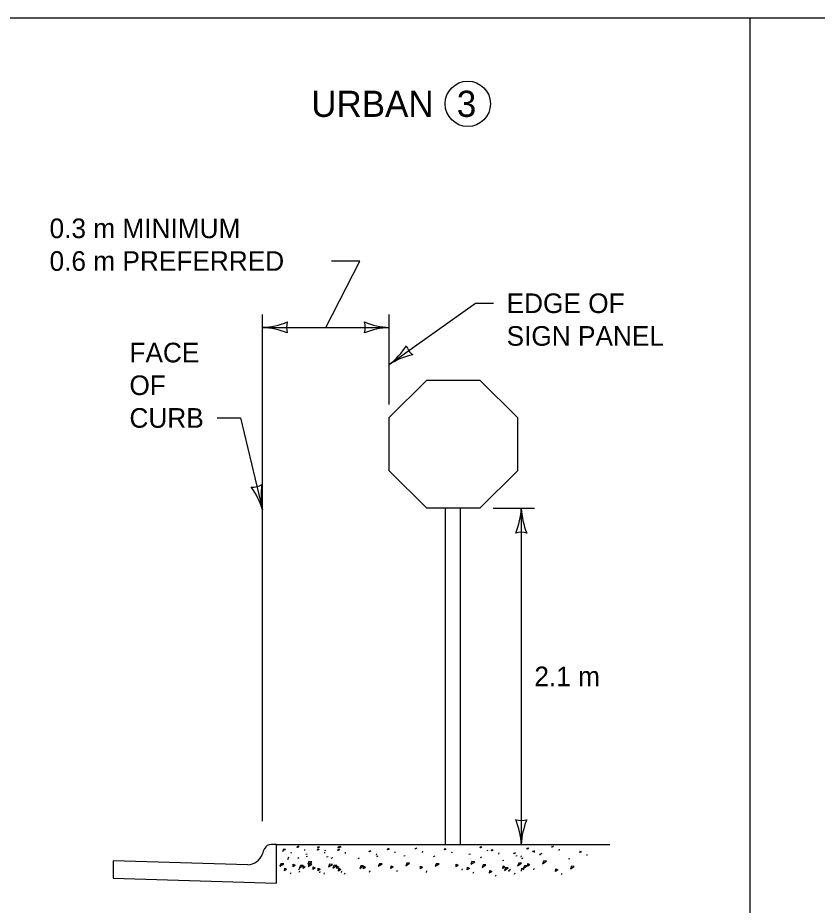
# Model space of a CAD drawing. Extents: x 49991.4 to 50021, y 49987.6 to 50011.4.
# Drawn here: x 50005.827 to 50008.273, y 49996.284 to 49998.999 of the extents above; entities that cross this region are included whole.
import ezdxf

# ---------------------------------------------------------------- set-up
doc = ezdxf.new("R2010")
doc.units = 0
for name, color, linetype in [('Level 1', 7, 'Continuous'), ('Level 2', 7, 'Continuous'), ('Level 3', 7, 'Continuous')]:
    doc.layers.add(name, color=color, linetype=linetype)

msp = doc.modelspace()

# ---------------------------------------------------------------- linework, layer by layer
at = {"layer": 'Level 1'}
for p, q in [((50007.1354, 49996.4699), (50007.1354, 49997.4987)), ((50007.1816, 49996.4699), (50007.1816, 49997.4987)), ((50006.6189, 49996.4699), (50006.6019, 49996.4699)), ((50006.6189, 49996.4699), (50007.6386, 49996.4699)), ((50006.6189, 49996.3514), (50006.6189, 49996.4699)), ((50006.6402, 49996.4554), (50006.637, 49996.4475)), ((50006.6411, 49996.4529), (50006.6431, 49996.4577)), ((50006.6456, 49996.454), (50006.6411, 49996.4529)), ((50006.6431, 49996.4577), (50006.6456, 49996.454)), ((50006.682, 49996.4609), (50006.684, 49996.4657)), ((50006.6865, 49996.462), (50006.682, 49996.4609)), ((50006.684, 49996.4657), (50006.6865, 49996.462)), ((50006.7049, 49996.4514), (50006.7054, 49996.455)), ((50006.7436, 49996.4529), (50006.7456, 49996.4577)), ((50006.7481, 49996.454), (50006.7436, 49996.4529)), ((50006.7449, 49996.46), (50006.7469, 49996.4648)), ((50006.7494, 49996.4611), (50006.7449, 49996.46)), ((50006.7456, 49996.4577), (50006.7481, 49996.454)), ((50006.7469, 49996.4648), (50006.7494, 49996.4611)), ((50006.7678, 49996.4505), (50006.7683, 49996.4541)), ((50006.8065, 49996.452), (50006.8085, 49996.4568)), ((50006.811, 49996.4531), (50006.8065, 49996.452)), ((50006.8074, 49996.46), (50006.8094, 49996.4648)), ((50006.8119, 49996.4611), (50006.8074, 49996.46)), ((50006.8085, 49996.4568), (50006.811, 49996.4531)), ((50006.8111, 49996.4609), (50006.8131, 49996.4657)), ((50006.8156, 49996.462), (50006.8111, 49996.4609)), ((50006.8131, 49996.4657), (50006.8156, 49996.462)), ((50006.9018, 49996.4473), (50006.9039, 49996.452)), ((50006.9039, 49996.452), (50006.9063, 49996.4484)), ((50006.9587, 49996.4537), (50006.9607, 49996.4585)), ((50006.9632, 49996.4548), (50006.9587, 49996.4537)), ((50006.9607, 49996.4585), (50006.9632, 49996.4548)), ((50007.0425, 49996.4553), (50007.0446, 49996.46)), ((50007.0446, 49996.46), (50007.047, 49996.4564)), ((50007.1326, 49996.4537), (50007.1347, 49996.4585)), ((50007.1371, 49996.4548), (50007.1326, 49996.4537)), ((50007.1347, 49996.4585), (50007.1371, 49996.4548)), ((50007.2416, 49996.46), (50007.2437, 49996.4648)), ((50007.2461, 49996.4611), (50007.2416, 49996.46)), ((50007.2437, 49996.4648), (50007.2461, 49996.4611)), ((50007.2646, 49996.4505), (50007.265, 49996.4541)), ((50007.276, 49996.4505), (50007.278, 49996.4552)), ((50007.2805, 49996.4515), (50007.276, 49996.4505)), ((50007.278, 49996.4552), (50007.2805, 49996.4515)), ((50007.385, 49996.4553), (50007.3871, 49996.46)), ((50007.3895, 49996.4564), (50007.385, 49996.4553)), ((50007.3871, 49996.46), (50007.3895, 49996.4564)), ((50007.4024, 49996.4473), (50007.4044, 49996.452)), ((50007.4044, 49996.452), (50007.4068, 49996.4484)), ((50007.4608, 49996.4616), (50007.4629, 49996.4663)), ((50007.4653, 49996.4627), (50007.4608, 49996.4616)), ((50007.4629, 49996.4663), (50007.4653, 49996.4627)), ((50007.4837, 49996.452), (50007.4842, 49996.4557)), ((50007.5462, 49996.4457), (50007.5483, 49996.4505)), ((50007.5483, 49996.4505), (50007.5507, 49996.4468)), ((50006.6551, 49996.4314), (50006.6519, 49996.4235)), ((50006.664, 49996.4433), (50006.6645, 49996.447)), ((50006.6871, 49996.4287), (50006.6824, 49996.4271)), ((50006.7128, 49996.4405), (50006.7082, 49996.4389)), ((50006.7136, 49996.4334), (50006.709, 49996.4318)), ((50006.7665, 49996.4433), (50006.767, 49996.447)), ((50006.7765, 49996.4325), (50006.7719, 49996.4309)), ((50006.7896, 49996.4287), (50006.7849, 49996.4271)), ((50006.8294, 49996.4424), (50006.8299, 49996.4461)), ((50006.8719, 49996.4278), (50006.8672, 49996.4262)), ((50006.9063, 49996.4484), (50006.9018, 49996.4473)), ((50006.9287, 49996.4342), (50006.9241, 49996.4326)), ((50006.9247, 49996.4377), (50006.9252, 49996.4414)), ((50006.9816, 49996.4441), (50006.9821, 49996.4478)), ((50007.0125, 49996.4358), (50007.0079, 49996.4342)), ((50007.0654, 49996.4457), (50007.0659, 49996.4494)), ((50007.1026, 49996.4342), (50007.098, 49996.4326)), ((50007.1555, 49996.4441), (50007.156, 49996.4478)), ((50007.2117, 49996.4405), (50007.2071, 49996.4389)), ((50007.246, 49996.4309), (50007.2414, 49996.4293)), ((50007.2989, 49996.4409), (50007.2994, 49996.4445)), ((50007.3444, 49996.441), (50007.3464, 49996.4457)), ((50007.3488, 49996.4421), (50007.3444, 49996.441)), ((50007.3464, 49996.4457), (50007.3488, 49996.4421)), ((50007.3551, 49996.4358), (50007.3504, 49996.4342)), ((50007.3673, 49996.4314), (50007.3678, 49996.435)), ((50007.3724, 49996.4278), (50007.3678, 49996.4262)), ((50007.4068, 49996.4484), (50007.4024, 49996.4473)), ((50007.4079, 49996.4457), (50007.4084, 49996.4494)), ((50007.4253, 49996.4377), (50007.4258, 49996.4414)), ((50007.4309, 49996.4421), (50007.4262, 49996.4405)), ((50007.5162, 49996.4262), (50007.5116, 49996.4246)), ((50007.5507, 49996.4468), (50007.5462, 49996.4457)), ((50007.5691, 49996.4361), (50007.5696, 49996.4398)), ((50006.5306, 49996.4081), (50006.1189, 49996.4205)), ((50006.1189, 49996.4205), (50006.1189, 49996.3665)), ((50006.6319, 49996.4112), (50006.6287, 49996.4033)), ((50006.6287, 49996.4033), (50006.6408, 49996.4109)), ((50006.6408, 49996.4109), (50006.6319, 49996.4112)), ((50006.6434, 49996.3897), (50006.6439, 49996.398)), ((50006.6439, 49996.398), (50006.6497, 49996.3947)), ((50006.6692, 49996.4016), (50006.6696, 49996.4098)), ((50006.6755, 49996.4065), (50006.6692, 49996.4016)), ((50006.6696, 49996.4098), (50006.6755, 49996.4065)), ((50006.6917, 49996.4056), (50006.6884, 49996.3977)), ((50006.6884, 49996.3977), (50006.7005, 49996.4054)), ((50006.7005, 49996.4054), (50006.6917, 49996.4056)), ((50006.7003, 49996.3962), (50006.7008, 49996.4044)), ((50006.7066, 49996.4011), (50006.7003, 49996.3962)), ((50006.7008, 49996.4044), (50006.7066, 49996.4011)), ((50006.7174, 49996.4175), (50006.7142, 49996.4096)), ((50006.7142, 49996.4096), (50006.7263, 49996.4172)), ((50006.7182, 49996.4104), (50006.715, 49996.4025)), ((50006.715, 49996.4025), (50006.7271, 49996.4101)), ((50006.7263, 49996.4172), (50006.7174, 49996.4175)), ((50006.7271, 49996.4101), (50006.7182, 49996.4104)), ((50006.7308, 49996.3936), (50006.7313, 49996.4018)), ((50006.7371, 49996.3985), (50006.7308, 49996.3936)), ((50006.7313, 49996.4018), (50006.7371, 49996.3985)), ((50006.7459, 49996.3897), (50006.7464, 49996.398)), ((50006.7464, 49996.398), (50006.7522, 49996.3947)), ((50006.7811, 49996.4095), (50006.7779, 49996.4016)), ((50006.7779, 49996.4016), (50006.79, 49996.4092)), ((50006.79, 49996.4092), (50006.7811, 49996.4095)), ((50006.7942, 49996.4056), (50006.7909, 49996.3977)), ((50006.7909, 49996.3977), (50006.803, 49996.4054)), ((50006.803, 49996.4054), (50006.7942, 49996.4056)), ((50006.8028, 49996.3962), (50006.8033, 49996.4044)), ((50006.8091, 49996.4011), (50006.8028, 49996.3962)), ((50006.8033, 49996.4044), (50006.8091, 49996.4011)), ((50006.8088, 49996.3888), (50006.8093, 49996.3971)), ((50006.8093, 49996.3971), (50006.8151, 49996.3938)), ((50006.8765, 49996.4047), (50006.8732, 49996.3968)), ((50006.8732, 49996.3968), (50006.8853, 49996.4045)), ((50006.8853, 49996.4045), (50006.8765, 49996.4047)), ((50006.8851, 49996.3953), (50006.8856, 49996.4035)), ((50006.8914, 49996.4002), (50006.8851, 49996.3953)), ((50006.8856, 49996.4035), (50006.8914, 49996.4002)), ((50006.9333, 49996.4112), (50006.9301, 49996.4033)), ((50006.9301, 49996.4033), (50006.9422, 49996.4109)), ((50006.9422, 49996.4109), (50006.9333, 49996.4112)), ((50006.9689, 49996.3968), (50006.9694, 49996.4051)), ((50006.9752, 49996.4018), (50006.9689, 49996.3968)), ((50006.9694, 49996.4051), (50006.9752, 49996.4018)), ((50007.0171, 49996.4127), (50007.0139, 49996.4048)), ((50007.0139, 49996.4048), (50007.026, 49996.4125)), ((50007.026, 49996.4125), (50007.0171, 49996.4127)), ((50007.059, 49996.3953), (50007.0595, 49996.4035)), ((50007.0653, 49996.4002), (50007.059, 49996.3953)), ((50007.0595, 49996.4035), (50007.0653, 49996.4002)), ((50007.1073, 49996.4112), (50007.104, 49996.4033)), ((50007.104, 49996.4033), (50007.1161, 49996.4109)), ((50007.1161, 49996.4109), (50007.1073, 49996.4112)), ((50007.168, 49996.4016), (50007.1685, 49996.4098)), ((50007.1743, 49996.4065), (50007.168, 49996.4016)), ((50007.1685, 49996.4098), (50007.1743, 49996.4065)), ((50007.2024, 49996.392), (50007.2028, 49996.4002)), ((50007.2087, 49996.397), (50007.2024, 49996.392)), ((50007.2028, 49996.4002), (50007.2087, 49996.397)), ((50007.2163, 49996.4175), (50007.213, 49996.4096)), ((50007.213, 49996.4096), (50007.2251, 49996.4172)), ((50007.2251, 49996.4172), (50007.2163, 49996.4175)), ((50007.2506, 49996.4079), (50007.2474, 49996.4)), ((50007.2474, 49996.4), (50007.2595, 49996.4076)), ((50007.2595, 49996.4076), (50007.2506, 49996.4079)), ((50007.3144, 49996.4215), (50007.3098, 49996.4199)), ((50007.3114, 49996.3968), (50007.3119, 49996.4051)), ((50007.3177, 49996.4018), (50007.3114, 49996.3968)), ((50007.3119, 49996.4051), (50007.3177, 49996.4018)), ((50007.319, 49996.3984), (50007.3157, 49996.3905)), ((50007.3157, 49996.3905), (50007.3279, 49996.3982)), ((50007.3279, 49996.3982), (50007.319, 49996.3984)), ((50007.3597, 49996.4127), (50007.3564, 49996.4048)), ((50007.3564, 49996.4048), (50007.3685, 49996.4125)), ((50007.3685, 49996.4125), (50007.3597, 49996.4127)), ((50007.3687, 49996.3888), (50007.3692, 49996.3971)), ((50007.3692, 49996.3971), (50007.375, 49996.3938)), ((50007.377, 49996.4047), (50007.3737, 49996.3968)), ((50007.3737, 49996.3968), (50007.3859, 49996.4045)), ((50007.3859, 49996.4045), (50007.377, 49996.4047)), ((50007.3872, 49996.4032), (50007.3877, 49996.4114)), ((50007.3935, 49996.4081), (50007.3872, 49996.4032)), ((50007.3877, 49996.4114), (50007.3935, 49996.4081)), ((50007.406, 49996.397), (50007.4044, 49996.3927)), ((50007.4355, 49996.419), (50007.4322, 49996.4112)), ((50007.4322, 49996.4112), (50007.4443, 49996.4188)), ((50007.4443, 49996.4188), (50007.4355, 49996.419)), ((50007.5208, 49996.4032), (50007.5176, 49996.3953)), ((50007.5176, 49996.3953), (50007.5297, 49996.4029)), ((50007.5297, 49996.4029), (50007.5208, 49996.4032)), ((50006.6497, 49996.3947), (50006.6434, 49996.3897)), ((50006.6622, 49996.3836), (50006.6606, 49996.3793)), ((50006.688, 49996.3954), (50006.6864, 49996.3911)), ((50006.6888, 49996.3883), (50006.6872, 49996.384)), ((50006.7522, 49996.3947), (50006.7459, 49996.3897)), ((50006.7517, 49996.3874), (50006.7501, 49996.3831)), ((50006.7647, 49996.3836), (50006.7631, 49996.3793)), ((50006.8151, 49996.3938), (50006.8088, 49996.3888)), ((50006.8179, 49996.3883), (50006.8163, 49996.384)), ((50006.8276, 49996.3827), (50006.826, 49996.3784)), ((50006.9039, 49996.3891), (50006.9023, 49996.3848)), ((50006.9877, 49996.3907), (50006.9861, 49996.3864)), ((50007.0778, 49996.3891), (50007.0762, 49996.3848)), ((50007.1868, 49996.3954), (50007.1852, 49996.3911)), ((50007.2212, 49996.3858), (50007.2196, 49996.3816)), ((50007.2707, 49996.3825), (50007.2712, 49996.3908)), ((50007.277, 49996.3875), (50007.2707, 49996.3825)), ((50007.2712, 49996.3908), (50007.277, 49996.3875)), ((50007.2895, 49996.3763), (50007.288, 49996.3721)), ((50007.3302, 49996.3907), (50007.3286, 49996.3864)), ((50007.335, 49996.3938), (50007.3287, 49996.3888)), ((50007.3475, 49996.3827), (50007.346, 49996.3784)), ((50007.4726, 49996.3873), (50007.4731, 49996.3955)), ((50007.4789, 49996.3922), (50007.4726, 49996.3873)), ((50007.4731, 49996.3955), (50007.4789, 49996.3922)), ((50007.4914, 49996.3811), (50007.4898, 49996.3768)), ((50006.1189, 49996.3665), (50006.6189, 49996.3514))]:
    msp.add_line(p, q, dxfattribs=at)
for points in [[(49999.3835, 49998.9992), (50016.7501, 49998.9992), (50016.7501, 49987.7988), (49999.3835, 49987.7988)], [(50007.0783, 49997.8908), (50007.2411, 49997.8908), (50007.3558, 49997.7761), (50007.3558, 49997.6134), (50007.2411, 49997.4987), (50007.0783, 49997.4987), (50006.9637, 49997.6134), (50006.9637, 49997.7761)]]:
    msp.add_lwpolyline(points, close=True, dxfattribs=at)
for centre, radius, start, end in [((50006.6266, 49996.4306), 0.0521, 148.1841, 167.8949), ((50006.6003, 49996.4505), 0.0194, 85.2356, 156.6889), ((50006.5301, 49996.4559), 0.0477, 270.5454, 342.4535)]:
    msp.add_arc(centre, radius, start, end, dxfattribs=at)
at = {"layer": 'Level 2'}
msp.add_circle((50007.2039, 49998.7359), 0.0693, dxfattribs=at)
at = {"layer": 'Level 3'}
for p, q in [((50008.0668, 49998.9992), (50008.0668, 49994.0732)), ((50006.7696, 49998.0517), (50006.8735, 49998.255)), ((50006.8735, 49998.255), (50006.7864, 49998.255)), ((50006.9636, 49997.9381), (50007.2272, 49998.1258)), ((50007.2272, 49998.1258), (50007.2826, 49998.1258)), ((50006.5757, 49996.5415), (50006.5757, 49998.0917)), ((50006.9636, 49997.8161), (50006.9636, 49998.0917)), ((50006.5757, 49998.0517), (50006.9636, 49998.0517)), ((50006.4369, 49997.7749), (50006.5089, 49997.7749)), ((50006.5089, 49997.7749), (50006.5757, 49997.4934)), ((50007.2811, 49997.4987), (50007.4075, 49997.4987)), ((50007.3675, 49997.4987), (50007.3675, 49996.4699))]:
    msp.add_line(p, q, dxfattribs=at)
for centre, radius, start, end in [((50006.5642, 49998.2844), 0.233, 272.8273, 292.0772), ((50006.7039, 49998.0517), 0.0548, 162.1388, 197.8612), ((50006.9728, 49998.2738), 0.2223, 247.456, 267.6395), ((50006.8354, 49998.0517), 0.0548, 342.1388, 17.8612), ((50006.5665, 49997.8296), 0.2223, 67.456, 87.6395), ((50006.9751, 49997.819), 0.233, 92.8273, 112.0772), ((50006.8193, 49998.121), 0.233, 308.2806, 327.5305), ((50007.068, 49998.0125), 0.0548, 197.5921, 233.3145), ((50007.085, 49997.7518), 0.2223, 102.9093, 123.0928), ((50006.5453, 49997.618), 0.0548, 265.8498, 301.5721), ((50006.3523, 49997.4271), 0.233, 16.5382, 35.7881), ((50006.7936, 49997.5372), 0.2223, 171.1669, 191.3505), ((50007.1454, 49997.5079), 0.2223, 337.456, 357.6395), ((50007.6002, 49997.5102), 0.233, 182.8273, 202.0772), ((50007.3675, 49997.3705), 0.0548, 72.1388, 107.8612), ((50007.3675, 49996.5981), 0.0548, 252.1388, 287.8612), ((50007.1348, 49996.4584), 0.233, 2.8273, 22.0772), ((50007.5896, 49996.4607), 0.2223, 157.456, 177.6395)]:
    msp.add_arc(centre, radius, start, end, dxfattribs=at)

# ---------------------------------------------------------------- texts
at = {"layer": 'Level 2'}
for s, height, p in [('URBAN', 0.08, (50006.7249, 49998.6959)), ('3', 0.08, (50007.1703, 49998.6959)), ('0.3 m MINIMUM', 0.06, (50005.9243, 49998.325)), ('0.6 m PREFERRED', 0.06, (50005.9243, 49998.225)), ('EDGE OF', 0.06, (50007.3226, 49998.0958)), ('SIGN PANEL', 0.06, (50007.3226, 49997.9958)), ('FACE', 0.06, (50006.1687, 49997.9449)), ('OF', 0.06, (50006.1687, 49997.8449)), ('CURB', 0.06, (50006.1687, 49997.7449)), ('2.1 m', 0.06, (50007.4075, 49996.9543))]:
    msp.add_text(s, height=height, dxfattribs=at).set_placement(p)

doc.saveas('drawing.dxf')
